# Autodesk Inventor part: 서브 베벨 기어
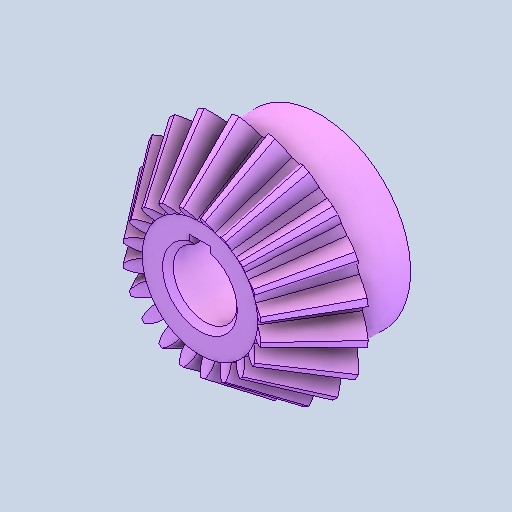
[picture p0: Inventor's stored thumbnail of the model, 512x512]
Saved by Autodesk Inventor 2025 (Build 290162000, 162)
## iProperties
Created: 2026-07
Part Number: 서브 베벨 기어
Material: 강철, 합금
Document SubType Name: Modeling
Designer: KDI
Density: 7.73 g/cm^3
Appearance: 기본값
Author: jhkim
Revision Number: 1
Sending System: Autodesk Inventor 2027
Preprocessor: ST-DEVELOPER v20.1
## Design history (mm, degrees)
node "복구된 형상1"
  node "스케치11"
feature "Solid1"
node "스케치10"
node "솔리드1"
